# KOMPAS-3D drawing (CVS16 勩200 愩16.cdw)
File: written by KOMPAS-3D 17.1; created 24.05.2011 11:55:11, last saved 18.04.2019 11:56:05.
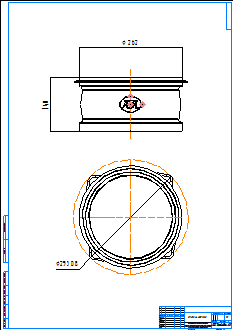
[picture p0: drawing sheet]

Title block, sheet 1: name: CVS16 Ду200 Ру16; material: Внимание! Данный продукт является объектом авторского права ООО «Торговый Дом АДЛ». / Запрещается изменение, копирование, распространение / (в том числе путем копирования на другие сайты и ресурсы в Интернете) / или любое иное использование информации и объектов без предварительного / согласия правообладателя (ООО «Торговый Дом АДЛ»).; scale: 1:1; sheets: 1; organisation: ООО "Торговый дом АДЛ"; sheet format: A1; stored path: \\adlc.lan\data\АДЛ_ПКД\3D-модели\ADL production\Клапаны обратные ГРАНЛОК\CVS16\KOMPAS 2D\CVS16 Ду200 Ру16.cdw

Views: Спереди 1, Проекционный вид 2
Dimensions and other numbers on the sheet: 140; 262; 293,08; 1:1; 1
